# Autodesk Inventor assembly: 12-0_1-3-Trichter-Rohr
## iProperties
Created: 2006-01
Part Number: 12-0_1-3-Trichter-Rohr
Document SubType Name: Assembly
Designer: Armin Gräf
Stock Number: 12-0_1-3-Trichter-Rohr
Author: Armin Gräf
